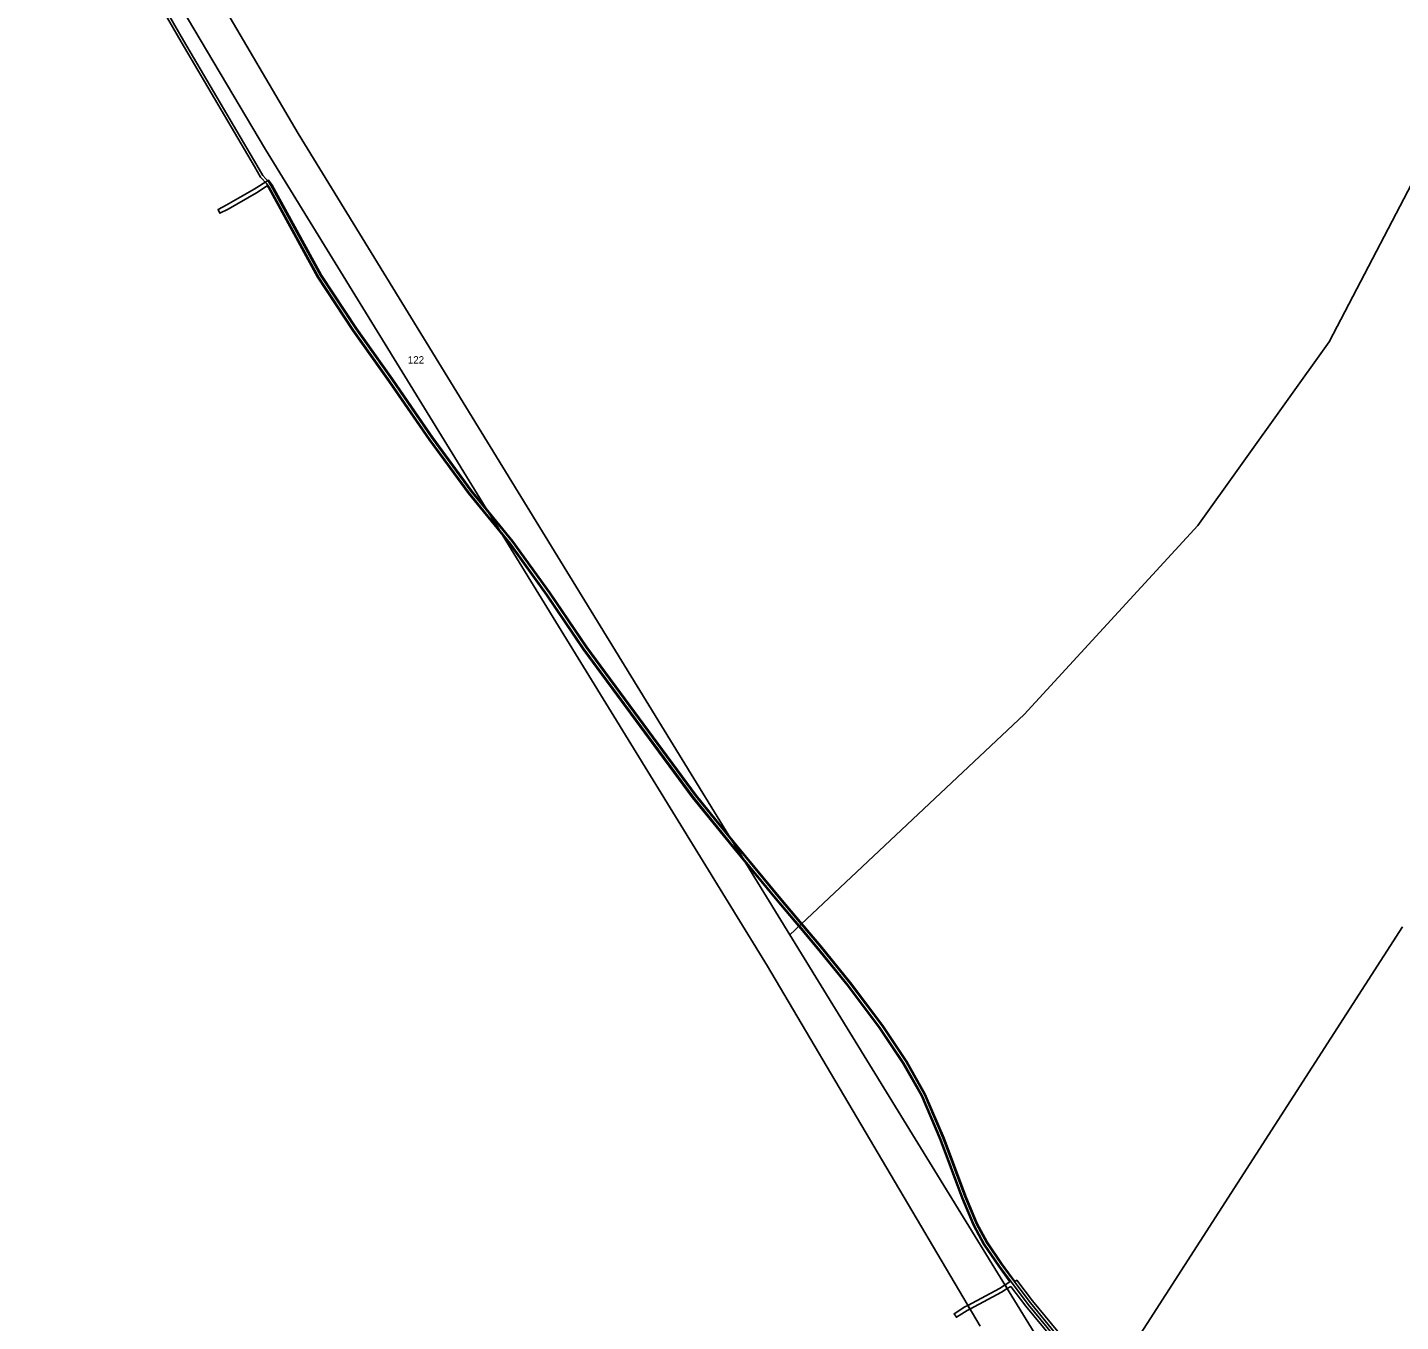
# Model space of a CAD drawing. Extents: x -752500 to -750336, y -1035826 to -1033500.
# Drawn here: x -751224 to -750904.8, y -1035019.2 to -1034718.3 of the extents above; entities that cross this region are included whole.
import ezdxf

# ---------------------------------------------------------------- set-up
doc = ezdxf.new("R2010")
doc.units = 0
for name, color, linetype in [('Hranice parcel', 7, 'Continuous'), ('Parcelní čísla', 7, 'Continuous'), ('Věcná břemena k části', 7, 'Continuous')]:
    doc.layers.add(name, color=color, linetype=linetype)

msp = doc.modelspace()

# ---------------------------------------------------------------- linework, layer by layer
at = {"layer": 'Hranice parcel'}
for p, q in [((-751161.12, -1034742.97), (-751278.23, -1034542.79)), ((-751219.84, -1034660.39), (-751168.66, -1034746.67)), ((-750885.14, -1034721.76), (-750921.44, -1034791.39)), ((-751161.12, -1034742.97), (-751074.5, -1034884.05)), ((-751168.66, -1034746.67), (-751051.96, -1034936.57)), ((-750921.44, -1034791.39), (-750951.94, -1034834.07)), ((-750951.94, -1034834.07), (-750992.35, -1034878.06)), ((-750992.35, -1034878.06), (-751046.76, -1034929.23)), ((-751074.5, -1034884.05), (-751046.76, -1034929.23)), ((-751046.76, -1034929.23), (-750987.88, -1035025.12)), ((-750904.38, -1034927.42), (-750974.16, -1035035.85)), ((-751051.96, -1034936.57), (-751002.58, -1035020.21))]:
    msp.add_line(p, q, dxfattribs=at)
at = {"layer": 'Věcná břemena k části'}
for p, q in [((-751113.45, -1034836.51), (-751117.39, -1034830.1)), ((-751114.24, -1034835.23), (-751116.59, -1034831.4)), ((-751116.59, -1034831.4), (-751114.24, -1034835.23)), ((-751059.92, -1034907.8), (-751057.65, -1034911.5)), ((-751057.65, -1034911.5), (-751059.92, -1034907.8)), ((-751049.73, -1034921.38), (-751056.89, -1034912.74)), ((-751048.97, -1034920.74), (-751043.99, -1034926.62)), ((-750996.23, -1035011.52), (-750996.75, -1035010.67)), ((-750996.75, -1035010.67), (-750996.23, -1035011.52)), ((-751005.41, -1035015.41), (-751004.91, -1035016.27)), ((-751004.91, -1035016.27), (-751005.41, -1035015.41))]:
    msp.add_line(p, q, dxfattribs=at)
for points in [[(-751114.24, -1034835.23), (-751121.36, -1034826.51), (-751130.47, -1034814.05), (-751139.83, -1034800.48), (-751148.2, -1034788.69), (-751156.39, -1034776.28), (-751167.85, -1034755.4), (-751168.36, -1034754.64), (-751169.82, -1034753.08), (-751171.23, -1034750.64), (-751188.3, -1034721.64), (-751199.28, -1034702.46), (-751206.92, -1034685.52), (-751212.7, -1034672.42)], [(-751210.16, -1034676.7), (-751206.38, -1034685.28), (-751198.74, -1034702.18), (-751187.78, -1034721.34), (-751170.71, -1034750.34), (-751169.34, -1034752.72), (-751167.9, -1034754.26), (-751167.33, -1034755.08), (-751155.87, -1034775.96), (-751147.7, -1034788.35), (-751139.33, -1034800.14), (-751129.99, -1034813.71), (-751120.88, -1034826.15), (-751116.59, -1034831.4)], [(-751113.45, -1034836.51), (-751121.52, -1034826.64), (-751130.64, -1034814.17), (-751139.99, -1034800.6), (-751148.36, -1034788.8), (-751156.56, -1034776.38), (-751168.02, -1034755.5), (-751168.27, -1034755.14), (-751170.77, -1034756.77), (-751177.34, -1034760.51), (-751179.27, -1034761.48), (-751179.71, -1034760.58), (-751177.82, -1034759.63), (-751171.29, -1034755.91), (-751167.99, -1034753.76), (-751167.16, -1034754.98), (-751155.7, -1034775.86), (-751147.54, -1034788.24), (-751139.17, -1034800.02), (-751129.82, -1034813.59), (-751120.72, -1034826.02), (-751117.39, -1034830.1)], [(-751117.39, -1034830.1), (-751116.59, -1034831.4), (-751113.45, -1034836.51)], [(-751117.39, -1034830.1), (-751111.17, -1034837.72), (-751102.53, -1034849.72), (-751094, -1034862.33), (-751068.58, -1034896.79), (-751060.75, -1034906.45)], [(-751116.59, -1034831.4), (-751111.33, -1034837.84), (-751102.69, -1034849.84), (-751094.16, -1034862.45), (-751068.74, -1034896.92), (-751059.92, -1034907.8)], [(-751057.65, -1034911.5), (-751059.68, -1034909.04), (-751069.22, -1034897.28), (-751094.66, -1034862.79), (-751103.19, -1034850.18), (-751111.81, -1034838.2), (-751114.24, -1034835.23)], [(-751056.89, -1034912.74), (-751059.84, -1034909.17), (-751069.38, -1034897.41), (-751094.82, -1034862.91), (-751103.35, -1034850.3), (-751111.97, -1034838.32), (-751113.45, -1034836.51)], [(-751060.75, -1034906.45), (-751059.06, -1034908.53), (-751048.97, -1034920.74)], [(-751056.89, -1034912.74), (-751057.65, -1034911.5), (-751059.92, -1034907.8), (-751060.75, -1034906.45)], [(-751060.75, -1034906.45), (-751057.65, -1034911.5), (-751056.89, -1034912.74)], [(-751059.92, -1034907.8), (-751059.22, -1034908.66), (-751049.12, -1034920.87), (-751044.14, -1034926.76), (-751039.72, -1034931.98), (-751032.83, -1034940.49), (-751025.36, -1034950.45), (-751019.76, -1034958.8), (-751015.48, -1034966.36), (-751011.11, -1034976.64), (-751006.07, -1034990.1), (-751003.39, -1034996.5)], [(-751003.93, -1034996.76), (-751006.63, -1034990.32), (-751011.67, -1034976.86), (-751016.02, -1034966.62), (-751020.28, -1034959.12), (-751025.84, -1034950.79), (-751033.31, -1034940.85), (-751040.18, -1034932.36), (-751044.57, -1034927.17), (-751049.58, -1034921.25), (-751057.65, -1034911.5)], [(-750996.75, -1035010.67), (-750995.62, -1035009.96), (-750998.23, -1035006.4), (-751001.77, -1035001.19), (-751004.11, -1034996.85), (-751006.81, -1034990.39), (-751011.85, -1034976.94), (-751016.2, -1034966.71), (-751020.45, -1034959.22), (-751026.01, -1034950.91), (-751033.46, -1034940.98), (-751040.34, -1034932.49), (-751044.72, -1034927.31), (-751049.73, -1034921.38)], [(-751043.99, -1034926.62), (-751039.56, -1034931.85), (-751032.68, -1034940.36), (-751025.19, -1034950.33), (-751019.59, -1034958.7), (-751015.3, -1034966.27), (-751010.93, -1034976.56), (-751005.89, -1034990.03), (-751003.21, -1034996.41), (-751000.91, -1035000.67), (-750997.41, -1035005.82), (-750994.48, -1035009.83)], [(-750957.8, -1035046.6), (-750960.45, -1035044.7), (-750973.2, -1035034.35), (-750976.9, -1035031.35), (-750979.02, -1035029.37), (-750985.47, -1035022.35), (-750991.36, -1035015.2), (-750998.06, -1035006.28), (-751001.6, -1035001.09), (-751003.93, -1034996.76)], [(-751003.39, -1034996.5), (-751001.08, -1035000.77), (-750997.58, -1035005.94), (-750990.88, -1035014.82), (-750985.01, -1035021.95), (-750978.6, -1035028.95), (-750976.5, -1035030.89), (-750972.87, -1035033.84), (-750960.09, -1035044.22), (-750952.93, -1035049.36)], [(-751005.41, -1035015.41), (-750998.07, -1035011.5), (-750996.75, -1035010.67)], [(-750996.23, -1035011.52), (-750997.57, -1035012.36), (-751004.91, -1035016.27)], [(-750962.54, -1035043.91), (-750973.58, -1035034.95), (-750977.36, -1035031.88), (-750979.52, -1035029.87), (-750985.99, -1035022.81), (-750991.9, -1035015.63), (-750995.44, -1035011.03), (-750996.23, -1035011.52)], [(-750994.48, -1035009.83), (-750994.05, -1035009.57), (-750990.34, -1035014.39), (-750984.49, -1035021.49), (-750978.1, -1035028.45), (-750976.04, -1035030.36), (-750972.48, -1035033.25), (-750959.66, -1035043.66), (-750948.37, -1035051.76), (-750942.8, -1035054.84), (-750930.81, -1035060.24), (-750917.87, -1035065.54), (-750905.26, -1035069.84)], [(-751004.91, -1035016.27), (-751005.58, -1035016.63), (-751008.05, -1035018.19), (-751008.59, -1035017.35), (-751006.08, -1035015.77), (-751005.41, -1035015.41)]]:
    msp.add_lwpolyline(points, dxfattribs=at)

# ---------------------------------------------------------------- texts
at = {"layer": 'Parcelní čísla'}
msp.add_text('122', height=1.7, dxfattribs=at).set_placement((-751135.6, -1034796.42))

doc.saveas('drawing.dxf')
